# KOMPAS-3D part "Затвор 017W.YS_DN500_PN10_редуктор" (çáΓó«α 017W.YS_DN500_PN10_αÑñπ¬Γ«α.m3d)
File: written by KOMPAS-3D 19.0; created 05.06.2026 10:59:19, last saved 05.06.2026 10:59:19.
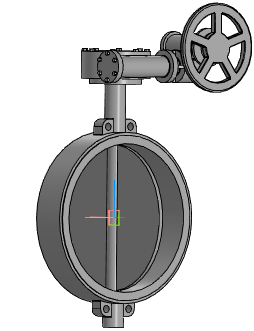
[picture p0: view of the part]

Document properties: Автор: Энергия; Полное имя файла: ..\..\..\3d для проектировщиков\x.x Тип 017W.Y(S) Затвор дисковый поворотный межфланцевый\Затвор 017W.Y(S)_DN50-DN1200_редуктор\Затвор 017W.YS_DN500_PN10_редуктор.a3d

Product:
- Part/product: Затвор 017W.YS_DN500_PN10_редуктор
    Масса: 165.157

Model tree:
1. Операция без истории:1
